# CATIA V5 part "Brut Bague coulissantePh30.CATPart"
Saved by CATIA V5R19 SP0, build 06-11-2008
Part number: Brut Ph30
Bounding box of the stored display mesh (mm): x -52.5 to 22.5, y -22.5 to 22.5, z -30 to 25
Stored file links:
  C:\Users\Laurent\Desktop\Sujet National E33\CFAO Catia\Brut Bague coulissantePh30.CATPart
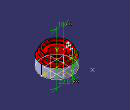
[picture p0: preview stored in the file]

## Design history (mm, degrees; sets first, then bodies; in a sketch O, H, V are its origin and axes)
Sketch1 on zx-plane, origin (0, 0, 0), H (-1, 0, 0), V (0, 0, 1)
  line L1 (10, 0) -> (22.5, 0)
  line L2 (22.5, 0) -> (22.5, 12.3803)
  line L3 (22.5, 12.3803) -> (20, 12.3803)
  line L4 (20, 12.3803) -> (20, 17.6003)
  line L5 (20, 17.6003) -> (17.75, 17.6003)
  arc A1 centre (17.7501, 17.9005) radius 0.3001 from (17.45, 17.9003) to (17.75, 17.6003) ccw
  line L6 (17.45, 17.9003) -> (17.45, 22.0803)
  arc A2 centre (17.1499, 22.0802) radius 0.3001 from (17.45, 22.0803) to (17.15, 22.3803) ccw
  line L7 (17.15, 22.3803) -> (14.95, 22.3803)
  line L8 (14.95, 22.3803) -> (14.95, 18.454)
  arc A3 centre (14.79, 17.9803) radius 0.5 from (14.79, 17.4803) to (14.95, 18.454) ccw
  line L9 (14.79, 17.4803) -> (10, 17.4803)
  line L10 (10, 17.4803) -> (10, 0)
  point P14 (52.5, -30)
  point P15 (10, -15)
  distance P14 L2 = 30
  distance P14 L1 = 30
  distance P15 L1 = 15
  distance P15 V = 10
  coincidence: P15 L10
Sketch2 on xy-plane, origin (0, 0, 0), H (1, 0, 0), V (0, 1, 0)
  circle A1 centre (0, 0) radius 22.5
  radius A1 = 22.5
Pad1: profile Sketch2, direction (0, 0, 1), length 25
Sketch3 on end face of Pad1, origin (0, 0, 25), H (1, 0, 0), V (0, 1, 0)
  circle A1 centre (0, 0) radius 10
  radius A1 = 10
Pocket1: profile Sketch3, direction (0, 0, -1), through (limit type 3)
Body1 (main body)
  Sketch4 on end face of Pad1, origin (0, 0, 25), H (1, 0, 0), V (0, 1, 0)
    circle A1 centre (0, 0) radius 17.45
    radius A1 = 17.45
  Pocket2: profile Sketch4, direction (0, 0, -1), length 4.78, outer side
  Sketch5 on end face of Pad1, origin (0, 0, 25), H (1, 0, 0), V (0, 1, 0)
    circle A1 centre (0, 0) radius 20
    radius A1 = 20
  Pocket3: profile Sketch5, direction (0, 0, -1), length 10, outer side
  Sketch6 on end face of Pad1, origin (0, 0, 25), H (1, 0, 0), V (0, 1, 0)
    circle A1 centre (0, 0) radius 14.95
    radius A1 = 14.95
  Pocket4: profile Sketch6, direction (0, 0, -1), length 4.78
  Sketch7 on zx-plane, origin (0, 0, 0), H (-1, 0, 0), V (0, 0, 1)
    axis line L1 (-25.6583, 20.6) -> (32.7674, 20.6)
    arc A1 centre (14.79, 20.6) radius 0.5 from (14.79, 20.1) to (14.79, 21.1) ccw
    point P3 (14.79, 20.6)
    reference projected line E1 (-17.45, 25) -> (17.45, 25) from edge [face of Pocket2 from Sketch4.A1 | end face of Pad1]
    line L2 (14.79, 20.1) -> (0, 20.1)
    point P4 (0, 20.1)
    line L3 (14.79, 21.1) -> (0, 21.1)
    point P5 (0, 21.1)
    line L4 (0, 20.1) -> (0, 21.1)
    reference projected line E2 through (0, 0) direction (0, 1) from axis of face of Pocket2 from Sketch4.A1
    distance L1 E1 = 4.4
    radius A1 = 0.5
    distance A1 E2 = 15.29
    horizontal: L1 H, L2 H, L3 H
    coincidence: P3 L1, P4 V, P5 V
    tangency: L3 A1, L2 A1
    vertical: L4 V
  Groove1: profile Sketch7, axis axis of face of Pocket3 from Sketch5.A1, angle 360
  Fillet1: radius 0.3, on edge [face of Pocket2 from Sketch4.A1 | end face of Pad1]; edge [end face of Pocket2 | face of Pocket2 from Sketch4.A1]
  Sketch8 on start face of Pad1, origin (0, 0, 0), H (1, 0, 0), V (0, -1, 0)
    circle A1 centre (0, 0) radius 23.7695
  Pocket5: profile Sketch8, direction (0, 0, 1), length 1.42, deactivated
  Sketch9 on end face of Pocket5, origin (0, 0, 1.42), H (1, 0, 0), V (0, -1, 0)
    circle A1 centre (0, 0) radius 17.9915
    radius A1 = 17.9915
  Pocket6: profile Sketch9, direction (0, 0, 1), length 14.8, outer side, deactivated
  Sketch10 on end face of Pocket5, origin (0, 0, 1.42), H (1, 0, 0), V (0, -1, 0)
    circle A1 centre (0, 0) radius 16.5
    radius A1 = 16.5
  Pocket7: profile Sketch10, direction (0, 0, 1), length 6.8, outer side, deactivated
  Chamfer1: length 1.5, angle 45, on edge [face of Pocket7 from Sketch10.A1 | end face of Pocket5], deactivated
  Sketch11 on zx-plane, origin (0, 0, 0), H (-1, 0, 0), V (0, 0, 1)
    line L1 (15.5, 8.22) -> (15.5, 6.72)
    line L2 (15.5, 6.72) -> (31.9529, 6.72)
    line L3 (15.5, 8.22) -> (31.9529, 8.22)
    line L4 (31.9529, 8.22) -> (31.9529, 6.72)
    reference projected line E1 (14.5, 1.42) -> (-14.5, 1.42) from edge [face of Chamfer1 | end face of Pocket5]
    reference projected line E2 through (0, 0) direction (0, -1) from axis of face of Pocket7 from Sketch10.A1
    distance L3 E1 = 6.8
    distance L1 E2 = 15.5
    distance L3 L2 = 1.5
    vertical: L1 V, L4 V
    horizontal: L2 H, L3 H
  Groove2: profile Sketch11, axis axis of face of Chamfer1, angle 360, deactivated
  Fillet2: radius 0.5, on edge [face of Groove2 from Sketch11.L1 | face of Groove2]; edge [face of Groove2 from Sketch11.L2 | face of Groove2 from Sketch11.L1], deactivated
  Sketch12 on end face of Pocket5, origin (0, 0, 1.42), H (1, 0, 0), V (0, -1, 0)
    circle A1 centre (0, 0) radius 14.2912
    radius A1 = 14.2912
  Pocket8: profile Sketch12, direction (0, 0, -1), through (limit type 3), deactivated
  Chamfer2: length 0.9, angle 30, on edge [end face of Pocket5 | face of Pocket8 from Sketch12.A1], deactivated
  Plane1: type Offset, Offset 19, RefPlane yz-plane
  Sketch13 on Plane1, origin (19, 0, 0), H (0, 1, 0), V (0, 0, 1)
    line L1 (-10, 18.22) -> (10, 18.22)
    line L2 (10, 18.22) -> (10, 14.8867)
    line L3 (10, 14.8867) -> (-10, 14.8867)
    line L4 (-10, 14.8867) -> (-10, 18.22)
    reference projected line E1 (20, 16.22) -> (-20, 16.22) from edge [face of Pocket3 from Sketch5.A1 | end face of Pocket6]
    reference projected line E2 through (0, 0) direction (0, -1) from axis of face of Pocket6 from Sketch9.A1
    reference projected line E3 through (0, 0) direction (0, -1) from axis of face of Pocket6 from Sketch9.A1
    distance L1 E1 = 2
    distance L2 E2 = 10
    distance L4 E3 = 10
    horizontal: L1 H, L3 H
    vertical: L2 V, L4 V
  Pocket9: profile Sketch13, direction (1, 0, 0), through (limit type 3), deactivated
  Mirror1: of Pocket9, about yz-plane, deactivated
  Sketch14 on start face of Pad1, origin (0, 0, 0), H (1, 0, 0), V (0, -1, 0)
    line L1 (0, 0) -> (-25.5551, 0)
    line L2 (-25.5551, 0) -> (-25.5551, 23.7969)
    line L3 (-25.5551, 23.7969) -> (0, 23.7969)
    line L4 (0, 23.7969) -> (0, 0)
    horizontal: L1 H, L3 H
    vertical: L2 V, L4 V
  Pocket10: profile Sketch14, direction (0, 0, 1), through (limit type 3), deactivated
Relations
  Body1.Offset = Sketch2.radius(A1)
  Body1.Offset = Sketch3.radius(A1)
